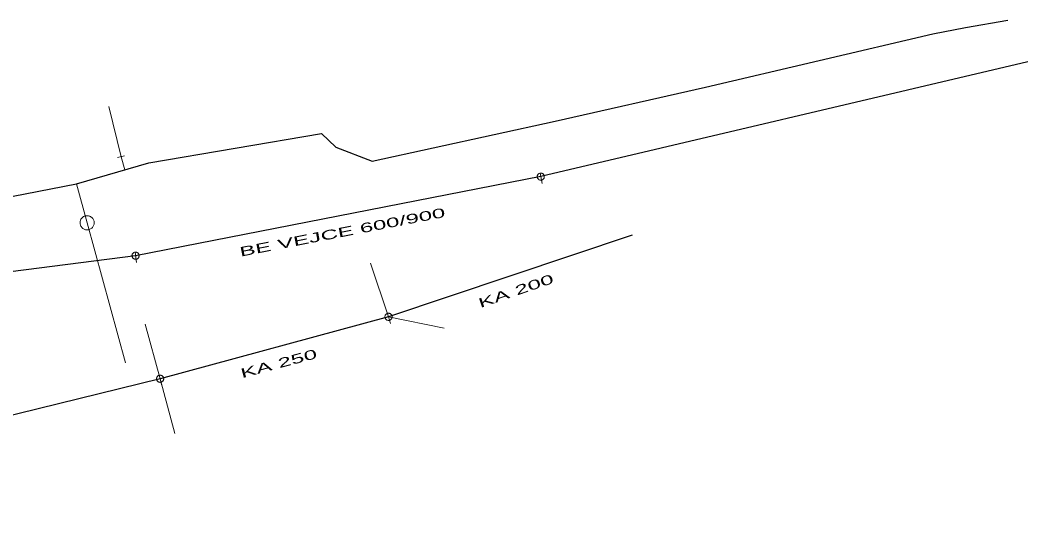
# Model space of a CAD drawing. Extents: x -791009 to -790862, y -978091 to -978015.
# Drawn here: x -790933 to -790861.8, y -978088 to -978051.9 of the extents above; entities that cross this region are included whole.
import ezdxf
from ezdxf.enums import TextEntityAlignment as Align

# ---------------------------------------------------------------- set-up
doc = ezdxf.new("R2010")
doc.units = 0
doc.header["$LTSCALE"] = 0.27
doc.layers.add('1', color=7, linetype='Continuous', lineweight=13)

msp = doc.modelspace()

# ---------------------------------------------------------------- linework, layer by layer
at = {"layer": '1', "lineweight": 25}
for p, q in [((-790861.809, -978054.85), (-790896.23, -978062.98)), ((-790896.23, -978062.98), (-790924.866, -978068.572)), ((-790889.778, -978067.113), (-790906.989, -978072.899)), ((-790924.866, -978068.572), (-790967.57, -978074.1)), ((-790906.989, -978072.899), (-790923.129, -978077.28)), ((-790923.129, -978077.28), (-790966.64, -978088.039))]:
    msp.add_line(p, q, dxfattribs=at)
at = {"layer": '1'}
for p, q in [((-790926.13, -978061.638), (-790925.649, -978061.519)), ((-790896.282, -978062.733), (-790896.127, -978063.461)), ((-790929.05, -978063.48), (-790928.291, -978066.245)), ((-790928.291, -978066.245), (-790925.574, -978076.144)), ((-790924.901, -978068.322), (-790924.797, -978069.059)), ((-790906.989, -978072.899), (-790908.265, -978069.109)), ((-790907.058, -978072.656), (-790906.853, -978073.371)), ((-790906.989, -978072.899), (-790903.068, -978073.692)), ((-790923.129, -978077.28), (-790924.177, -978073.42)), ((-790923.189, -978077.035), (-790923.009, -978077.757)), ((-790923.129, -978077.28), (-790922.081, -978081.14))]:
    msp.add_line(p, q, dxfattribs=at)
at = {"layer": '1', "lineweight": 25}
msp.add_lwpolyline([(-790938.133, -978065.27), (-790929.05, -978063.48), (-790923.92, -978062), (-790911.73, -978059.93), (-790910.719, -978060.899), (-790908.14, -978061.89), (-790895.21, -978059.059), (-790884.6, -978056.66), (-790868.534, -978052.874), (-790866.21, -978052.43), (-790863.219, -978051.91)], dxfattribs=at)
at = {"layer": '1'}
msp.add_lwpolyline([(-790925.627, -978062.491), (-790925.89, -978061.579), (-790926.761, -978058.008)], dxfattribs=at)
for points in [[(-790895.983, -978062.927), (-790895.99, -978062.902), (-790896, -978062.877), (-790896.011, -978062.853), (-790896.026, -978062.832), (-790896.042, -978062.811), (-790896.061, -978062.792), (-790896.082, -978062.775), (-790896.103, -978062.761), (-790896.127, -978062.749), (-790896.152, -978062.74), (-790896.178, -978062.733), (-790896.203, -978062.729), (-790896.23, -978062.728), (-790896.256, -978062.73), (-790896.282, -978062.733), (-790896.307, -978062.74), (-790896.332, -978062.75), (-790896.356, -978062.761), (-790896.378, -978062.776), (-790896.398, -978062.792), (-790896.417, -978062.811), (-790896.434, -978062.832), (-790896.448, -978062.853), (-790896.46, -978062.877), (-790896.469, -978062.902), (-790896.476, -978062.928), (-790896.48, -978062.953), (-790896.482, -978062.98), (-790896.48, -978063.006), (-790896.476, -978063.032), (-790896.47, -978063.057), (-790896.46, -978063.082), (-790896.448, -978063.106), (-790896.433, -978063.128), (-790896.417, -978063.148), (-790896.398, -978063.167), (-790896.377, -978063.184), (-790896.356, -978063.198), (-790896.332, -978063.21), (-790896.307, -978063.219), (-790896.282, -978063.226), (-790896.256, -978063.23), (-790896.229, -978063.232), (-790896.203, -978063.23), (-790896.177, -978063.226), (-790896.152, -978063.22), (-790896.127, -978063.21), (-790896.103, -978063.198), (-790896.082, -978063.183), (-790896.061, -978063.167), (-790896.042, -978063.148), (-790896.025, -978063.127), (-790896.011, -978063.106), (-790895.999, -978063.082), (-790895.99, -978063.057), (-790895.983, -978063.032), (-790895.979, -978063.006), (-790895.978, -978062.979), (-790895.98, -978062.953)], [(-790927.791, -978066.245), (-790927.794, -978066.193), (-790927.802, -978066.141), (-790927.816, -978066.091), (-790927.833, -978066.042), (-790927.858, -978065.995), (-790927.887, -978065.951), (-790927.919, -978065.911), (-790927.956, -978065.874), (-790927.997, -978065.841), (-790928.041, -978065.812), (-790928.088, -978065.788), (-790928.137, -978065.77), (-790928.186, -978065.756), (-790928.239, -978065.748), (-790928.291, -978065.745), (-790928.343, -978065.748), (-790928.395, -978065.756), (-790928.446, -978065.77), (-790928.494, -978065.788), (-790928.541, -978065.812), (-790928.585, -978065.841), (-790928.625, -978065.874), (-790928.663, -978065.911), (-790928.696, -978065.951), (-790928.723, -978065.995), (-790928.748, -978066.042), (-790928.767, -978066.091), (-790928.779, -978066.141), (-790928.788, -978066.193), (-790928.791, -978066.245), (-790928.788, -978066.297), (-790928.779, -978066.349), (-790928.767, -978066.4), (-790928.748, -978066.448), (-790928.723, -978066.495), (-790928.696, -978066.539), (-790928.663, -978066.58), (-790928.625, -978066.617), (-790928.585, -978066.65), (-790928.541, -978066.678), (-790928.494, -978066.702), (-790928.446, -978066.721), (-790928.395, -978066.733), (-790928.343, -978066.742), (-790928.291, -978066.745), (-790928.239, -978066.742), (-790928.186, -978066.733), (-790928.137, -978066.721), (-790928.088, -978066.702), (-790928.041, -978066.678), (-790927.997, -978066.65), (-790927.956, -978066.617), (-790927.919, -978066.58), (-790927.887, -978066.539), (-790927.858, -978066.495), (-790927.833, -978066.448), (-790927.816, -978066.4), (-790927.802, -978066.349), (-790927.794, -978066.297)], [(-790924.616, -978068.536), (-790924.622, -978068.511), (-790924.629, -978068.486), (-790924.639, -978068.461), (-790924.652, -978068.438), (-790924.667, -978068.416), (-790924.684, -978068.397), (-790924.704, -978068.378), (-790924.724, -978068.363), (-790924.747, -978068.349), (-790924.771, -978068.338), (-790924.797, -978068.33), (-790924.822, -978068.323), (-790924.848, -978068.321), (-790924.875, -978068.32), (-790924.901, -978068.322), (-790924.926, -978068.328), (-790924.951, -978068.335), (-790924.976, -978068.345), (-790925, -978068.358), (-790925.021, -978068.373), (-790925.04, -978068.39), (-790925.059, -978068.41), (-790925.074, -978068.43), (-790925.088, -978068.453), (-790925.099, -978068.477), (-790925.107, -978068.503), (-790925.114, -978068.528), (-790925.117, -978068.554), (-790925.118, -978068.581), (-790925.115, -978068.607), (-790925.11, -978068.632), (-790925.103, -978068.657), (-790925.092, -978068.682), (-790925.079, -978068.706), (-790925.064, -978068.727), (-790925.047, -978068.746), (-790925.027, -978068.765), (-790925.007, -978068.78), (-790924.984, -978068.794), (-790924.96, -978068.805), (-790924.935, -978068.814), (-790924.909, -978068.82), (-790924.883, -978068.823), (-790924.856, -978068.824), (-790924.83, -978068.821), (-790924.805, -978068.816), (-790924.78, -978068.809), (-790924.755, -978068.798), (-790924.732, -978068.785), (-790924.71, -978068.77), (-790924.691, -978068.753), (-790924.672, -978068.733), (-790924.657, -978068.713), (-790924.643, -978068.69), (-790924.632, -978068.666), (-790924.623, -978068.641), (-790924.617, -978068.615), (-790924.615, -978068.589), (-790924.614, -978068.562)], [(-790906.746, -978072.829), (-790906.755, -978072.805), (-790906.766, -978072.781), (-790906.779, -978072.757), (-790906.796, -978072.737), (-790906.814, -978072.717), (-790906.833, -978072.7), (-790906.855, -978072.685), (-790906.878, -978072.672), (-790906.902, -978072.662), (-790906.927, -978072.654), (-790906.954, -978072.649), (-790906.98, -978072.646), (-790907.006, -978072.648), (-790907.032, -978072.651), (-790907.058, -978072.656), (-790907.082, -978072.665), (-790907.106, -978072.676), (-790907.13, -978072.689), (-790907.151, -978072.706), (-790907.17, -978072.724), (-790907.187, -978072.743), (-790907.202, -978072.765), (-790907.215, -978072.788), (-790907.225, -978072.812), (-790907.233, -978072.837), (-790907.238, -978072.864), (-790907.241, -978072.89), (-790907.24, -978072.917), (-790907.237, -978072.943), (-790907.231, -978072.968), (-790907.223, -978072.993), (-790907.212, -978073.017), (-790907.198, -978073.04), (-790907.181, -978073.061), (-790907.163, -978073.08), (-790907.144, -978073.097), (-790907.122, -978073.112), (-790907.099, -978073.125), (-790907.075, -978073.135), (-790907.05, -978073.143), (-790907.024, -978073.148), (-790906.997, -978073.151), (-790906.97, -978073.15), (-790906.944, -978073.147), (-790906.919, -978073.141), (-790906.894, -978073.133), (-790906.87, -978073.122), (-790906.847, -978073.108), (-790906.827, -978073.091), (-790906.807, -978073.073), (-790906.79, -978073.054), (-790906.775, -978073.032), (-790906.762, -978073.009), (-790906.752, -978072.985), (-790906.744, -978072.96), (-790906.739, -978072.934), (-790906.736, -978072.907), (-790906.738, -978072.881), (-790906.741, -978072.855)], [(-790922.884, -978077.219), (-790922.892, -978077.194), (-790922.902, -978077.17), (-790922.914, -978077.146), (-790922.93, -978077.125), (-790922.947, -978077.105), (-790922.966, -978077.087), (-790922.988, -978077.07), (-790923.01, -978077.057), (-790923.034, -978077.046), (-790923.059, -978077.037), (-790923.085, -978077.032), (-790923.111, -978077.028), (-790923.138, -978077.028), (-790923.164, -978077.031), (-790923.189, -978077.035), (-790923.214, -978077.043), (-790923.238, -978077.053), (-790923.262, -978077.065), (-790923.284, -978077.081), (-790923.303, -978077.098), (-790923.321, -978077.117), (-790923.338, -978077.139), (-790923.351, -978077.161), (-790923.362, -978077.185), (-790923.371, -978077.21), (-790923.376, -978077.236), (-790923.38, -978077.262), (-790923.381, -978077.289), (-790923.378, -978077.315), (-790923.373, -978077.34), (-790923.366, -978077.365), (-790923.356, -978077.39), (-790923.343, -978077.413), (-790923.327, -978077.435), (-790923.31, -978077.454), (-790923.291, -978077.472), (-790923.269, -978077.489), (-790923.247, -978077.502), (-790923.223, -978077.513), (-790923.198, -978077.522), (-790923.173, -978077.528), (-790923.146, -978077.531), (-790923.119, -978077.532), (-790923.093, -978077.529), (-790923.068, -978077.524), (-790923.043, -978077.517), (-790923.018, -978077.507), (-790922.995, -978077.494), (-790922.974, -978077.478), (-790922.954, -978077.461), (-790922.936, -978077.442), (-790922.919, -978077.42), (-790922.906, -978077.398), (-790922.895, -978077.374), (-790922.886, -978077.349), (-790922.88, -978077.324), (-790922.877, -978077.297), (-790922.877, -978077.27), (-790922.88, -978077.244)]]:
    msp.add_lwpolyline(points, close=True, dxfattribs=at)

# ---------------------------------------------------------------- texts
at = {"layer": '1', "width": 1.9}
for s, rotation, p in [('BE VEJCE 600/900', 11, (-790910.189, -978067.234)), ('KA 200', 19, (-790897.877, -978071.379)), ('KA 250', 15, (-790914.661, -978076.522))]:
    msp.add_text(s, height=0.6667, rotation=rotation, dxfattribs=at).set_placement(p, align=Align.CENTER)

doc.saveas('drawing.dxf')
